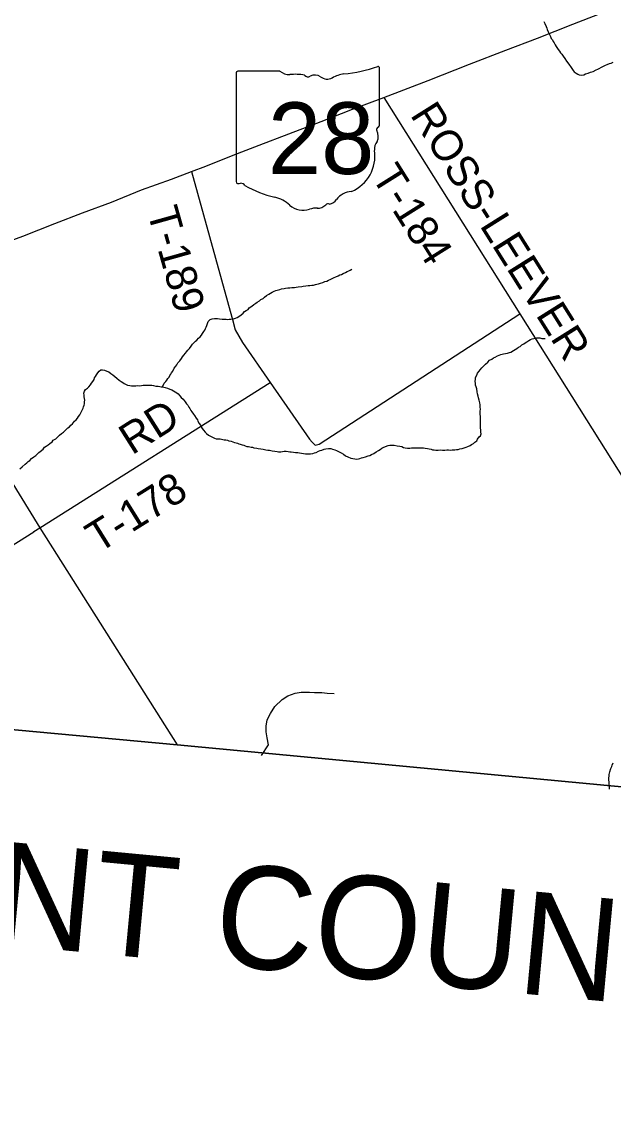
# Model space of a CAD drawing. Extents: x 1310247 to 1664935, y 284496 to 704931.
# Drawn here: x 1527609 to 1533358, y 458214 to 468911 of the extents above; entities that cross this region are included whole.
import ezdxf

# ---------------------------------------------------------------- set-up
doc = ezdxf.new("R2010")
doc.units = 0
for name, color, linetype in [('GM_X_Adjacent_County', 7, 'Continuous'), ('GM_X_Adjacent_County_Text', 7, 'Continuous'), ('GM_X_Airport_Class_2', 7, 'Continuous'), ('GM_X_County_Subdivision_Text', 7, 'Continuous'), ('GM_X_Interstate_Shield', 7, 'Continuous'), ('GM_X_Minor_Lake', 7, 'Continuous'), ('GM_X_Minor_River_Text', 7, 'Continuous'), ('GM_X_Township', 7, 'Continuous'), ('GM_X_Township_Subdivision', 7, 'Continuous'), ('GM_X_Unincorporated_Location', 7, 'Continuous')]:
    doc.layers.add(name, color=color, linetype=linetype)

msp = doc.modelspace()

# ---------------------------------------------------------------- linework, layer by layer
at = {"layer": 'GM_X_Adjacent_County'}
msp.add_lwpolyline([(1543818, 482923), (1543136, 476031), (1542849, 473143), (1542090, 465215), (1541846, 462655), (1541796, 462135), (1541666, 460788), (1541653, 460642), (1541041, 460701), (1540690, 460735), (1539583, 460843), (1534847, 461340), (1529119, 461882), (1524835, 462277), (1522527, 462501), (1521474, 462603)], dxfattribs=at)
at = {"layer": 'GM_X_Adjacent_County_Text'}
msp.add_lwpolyline([(1521474, 462603), (1522527, 462501), (1524835, 462277), (1529119, 461882), (1534847, 461340), (1539583, 460843), (1540690, 460735), (1541041, 460701), (1541653, 460642), (1544018, 460420), (1546591, 460177), (1546362, 457943), (1546170, 456232), (1545962, 454406), (1545594, 451170), (1544985, 445811), (1544696, 443260)], dxfattribs=at)
at = {"layer": 'GM_X_Airport_Class_2'}
for p, q in [((1529694, 468415), (1529694, 467359)), ((1530116, 468434), (1529708, 468434)), ((1531086, 467907), (1531086, 468460)), ((1531086, 467907), (1531086, 467907))]:
    msp.add_line(p, q, dxfattribs=at)
for centre, radius, start, end in [((1529710, 468418), 16.1, 98.1301, 188.1301), ((1530213, 468556), 156, 231.6195, 271.1119), ((1530265, 467840), 562, 80.4867, 94.9883), ((1530458, 468301), 93.8, 54.4667, 119.1411), ((1530779, 468111), 297, 97.3462, 120.7689), ((1530591, 469874), 1476, 275.8445, 288.9065), ((1531071, 468462), 15.5, 351.8621, 97.738), ((1530392, 468423), 45.1, 219.7921, 297.1024), ((1530580, 468469), 113, 233.8562, 294.8282), ((1531083, 467866), 24, 107.944, 210.337), ((1531070, 467905), 16.6, 289.6038, 7.7341), ((1530930, 467797), 144, 340.033, 23.6496), ((1530673, 467605), 369, 292.3089, 8.9858), ((1531142, 467676), 105, 136.8065, 186.9296), ((1529710, 467357), 16.3, 171.9584, 258.3066), ((1529713, 467465), 124, 267.339, 280.6039), ((1529738, 467298), 44.8, 29.7484, 93.2717), ((1530304, 468247), 1066, 240.4129, 257.1985), ((1530829, 467062), 202, 94.4031, 142.5768), ((1529986, 466884), 334, 47.1842, 75.836), ((1530347, 467293), 212, 230.7004, 286.2918), ((1530484, 467213), 113, 268.777, 315.5493), ((1530586, 467111), 31.8, 65.7517, 132.6484), ((1530573, 467256), 119, 282.8732, 323.2771), ((1530469, 466927), 174, 85.6951, 111.2099)]:
    msp.add_arc(centre, radius, start, end, dxfattribs=at)
at = {"layer": 'GM_X_County_Subdivision_Text'}
for points in [[(1531129, 468176), (1532451, 466074), (1535210, 461689)], [(1529258, 467457), (1529667, 465982)], [(1526336, 466341), (1526336, 466341), (1527783, 463992), (1529119, 461882)], [(1529667, 465982), (1529667, 465980), (1529684, 465919), (1529753, 465793), (1530022, 465405), (1530405, 464855), (1530432, 464824), (1530462, 464796), (1530500, 464807), (1532451, 466074)], [(1527724, 463955), (1527783, 463992), (1530022, 465405)], [(1524835, 462277), (1525361, 462592), (1525430, 462635), (1525465, 462681), (1525590, 462787), (1525745, 462831), (1525930, 462854), (1526108, 462936), (1527723, 463954), (1527724, 463955)]]:
    msp.add_lwpolyline(points, dxfattribs=at)
at = {"layer": 'GM_X_Interstate_Shield'}
msp.add_lwpolyline([(1527342, 466727), (1527618, 466829), (1527930, 466951), (1528199, 467054), (1528480, 467158), (1528773, 467280), (1529062, 467383), (1529258, 467457), (1529396, 467510), (1529663, 467617), (1529915, 467712), (1530205, 467824), (1530518, 467944), (1530824, 468064), (1531129, 468176), (1531559, 468342), (1531962, 468500), (1532316, 468638), (1532622, 468754), (1532966, 468889), (1533328, 469029)], dxfattribs=at)
at = {"layer": 'GM_X_Minor_River_Text'}
for points in [[(1532684, 468916), (1532694, 468896), (1532707, 468867), (1532715, 468851), (1532718, 468837), (1532728, 468816), (1532737, 468796), (1532749, 468770), (1532758, 468752), (1532768, 468737), (1532776, 468721), (1532787, 468707), (1532795, 468688), (1532805, 468672), (1532824, 468642), (1532836, 468627), (1532847, 468611), (1532859, 468597), (1532873, 468580), (1532888, 468556), (1532906, 468531), (1532919, 468515), (1532935, 468492), (1532944, 468478), (1532956, 468460), (1532972, 468439), (1532981, 468425), (1533001, 468413), (1533015, 468404), (1533029, 468398), (1533053, 468393), (1533073, 468397), (1533091, 468406), (1533116, 468414), (1533140, 468423), (1533166, 468431)], [(1533166, 468431), (1533195, 468446), (1533209, 468452), (1533223, 468459), (1533246, 468471), (1533272, 468486), (1533286, 468492), (1533302, 468496), (1533323, 468507), (1533339, 468511), (1533359, 468520)], [(1530608, 466408), (1530627, 466417), (1530645, 466425), (1530663, 466432), (1530686, 466442), (1530700, 466452), (1530716, 466455), (1530734, 466465), (1530757, 466474), (1530773, 466484), (1530787, 466492), (1530802, 466499), (1530818, 466509)], [(1528977, 465362), (1528992, 465399), (1529007, 465415), (1529017, 465429), (1529029, 465445), (1529040, 465458), (1529048, 465472), (1529057, 465486), (1529065, 465500), (1529077, 465516), (1529090, 465545), (1529107, 465563), (1529117, 465577), (1529126, 465595), (1529144, 465616), (1529161, 465640), (1529169, 465656), (1529184, 465670), (1529200, 465691), (1529209, 465705), (1529221, 465719), (1529238, 465736), (1529254, 465758), (1529269, 465778), (1529281, 465792), (1529296, 465807), (1529310, 465817), (1529325, 465837), (1529341, 465850), (1529355, 465866), (1529364, 465882), (1529378, 465900), (1529389, 465915), (1529395, 465929), (1529402, 465945), (1529406, 465959), (1529413, 465979), (1529419, 465997), (1529440, 466017), (1529460, 466026), (1529482, 466028), (1529496, 466027), (1529510, 466027), (1529532, 466024), (1529558, 466022), (1529580, 466021), (1529596, 466021), (1529610, 466018), (1529624, 466020), (1529641, 466020), (1529667, 466025), (1529687, 466031), (1529701, 466038), (1529720, 466048), (1529742, 466063), (1529761, 466081), (1529775, 466095), (1529791, 466106), (1529808, 466116), (1529818, 466130), (1529845, 466149), (1529863, 466165), (1529884, 466176), (1529898, 466188), (1529918, 466200), (1529933, 466211), (1529955, 466223), (1529969, 466236), (1529988, 466250), (1530010, 466264), (1530027, 466275), (1530043, 466283), (1530063, 466294), (1530077, 466300), (1530092, 466304), (1530116, 466311), (1530134, 466315), (1530160, 466320), (1530174, 466322), (1530195, 466325), (1530213, 466327), (1530233, 466328), (1530261, 466330), (1530275, 466331), (1530297, 466335), (1530330, 466338), (1530344, 466342), (1530370, 466345), (1530394, 466349), (1530408, 466348), (1530430, 466352), (1530446, 466353), (1530463, 466357), (1530477, 466361), (1530493, 466366), (1530513, 466370), (1530535, 466377), (1530556, 466387), (1530574, 466392), (1530592, 466400), (1530608, 466408)], [(1532038, 465316), (1532032, 465344), (1532027, 465364), (1532021, 465380), (1532020, 465398), (1532018, 465415), (1532019, 465439), (1532021, 465453), (1532032, 465476), (1532040, 465496), (1532055, 465516), (1532067, 465530), (1532082, 465549), (1532098, 465565), (1532119, 465583), (1532139, 465602), (1532158, 465622), (1532180, 465633), (1532195, 465645), (1532211, 465653), (1532235, 465664), (1532251, 465670), (1532268, 465677), (1532292, 465683), (1532312, 465686), (1532332, 465692), (1532351, 465697), (1532365, 465701), (1532391, 465715), (1532405, 465726), (1532424, 465736), (1532438, 465748), (1532454, 465757), (1532471, 465771), (1532489, 465782), (1532504, 465792), (1532520, 465802), (1532538, 465813), (1532555, 465823), (1532573, 465831), (1532587, 465834), (1532601, 465838), (1532615, 465840), (1532629, 465839), (1532647, 465839), (1532665, 465834), (1532683, 465832), (1532699, 465834)], [(1527589, 464566), (1527612, 464586), (1527641, 464611), (1527655, 464623), (1527671, 464637), (1527686, 464648), (1527702, 464666), (1527723, 464681), (1527745, 464697), (1527760, 464713), (1527772, 464726), (1527786, 464734), (1527815, 464758), (1527829, 464775), (1527846, 464787), (1527864, 464798), (1527881, 464812), (1527903, 464830), (1527914, 464843), (1527938, 464859), (1527957, 464878), (1527973, 464892), (1527994, 464908), (1528012, 464923), (1528030, 464939), (1528055, 464964), (1528072, 464974), (1528084, 464992), (1528102, 465005), (1528121, 465029), (1528136, 465043), (1528148, 465058), (1528158, 465076), (1528171, 465092), (1528181, 465110), (1528192, 465130), (1528203, 465155), (1528209, 465169), (1528213, 465185), (1528216, 465199), (1528218, 465217), (1528219, 465235), (1528217, 465251), (1528215, 465266), (1528214, 465282), (1528212, 465302), (1528217, 465320), (1528227, 465337), (1528246, 465351), (1528260, 465363), (1528277, 465384), (1528285, 465398), (1528298, 465416), (1528310, 465436), (1528316, 465450), (1528325, 465464), (1528335, 465481), (1528348, 465499), (1528360, 465515), (1528375, 465527), (1528393, 465528), (1528411, 465526), (1528435, 465517), (1528453, 465509), (1528474, 465494), (1528492, 465480), (1528512, 465465), (1528533, 465446), (1528555, 465428), (1528573, 465415), (1528589, 465405), (1528602, 465397), (1528616, 465390), (1528636, 465380), (1528658, 465375), (1528676, 465373), (1528702, 465372), (1528716, 465374), (1528736, 465375), (1528752, 465373), (1528771, 465375), (1528787, 465378), (1528805, 465380), (1528827, 465381)], [(1528827, 465381), (1528847, 465381), (1528871, 465378), (1528889, 465376), (1528911, 465371), (1528935, 465369), (1528949, 465366), (1528963, 465364), (1528977, 465362), (1529001, 465357), (1529025, 465350), (1529047, 465342), (1529067, 465333), (1529083, 465325), (1529099, 465314), (1529116, 465304), (1529130, 465294), (1529146, 465275), (1529159, 465261), (1529177, 465242), (1529195, 465218), (1529208, 465199), (1529222, 465185), (1529233, 465167), (1529241, 465152), (1529253, 465134), (1529262, 465120), (1529278, 465097), (1529288, 465083), (1529303, 465059), (1529315, 465042), (1529320, 465028), (1529334, 465008), (1529346, 464989), (1529353, 464975), (1529363, 464959), (1529374, 464941), (1529390, 464922), (1529404, 464908), (1529423, 464893), (1529449, 464879), (1529483, 464864), (1529497, 464859), (1529511, 464859), (1529537, 464856), (1529551, 464854), (1529575, 464849), (1529593, 464847), (1529607, 464845), (1529621, 464838), (1529645, 464834), (1529661, 464829), (1529675, 464823), (1529691, 464819), (1529705, 464814), (1529719, 464810), (1529733, 464806), (1529751, 464799), (1529767, 464795), (1529781, 464790), (1529796, 464784), (1529812, 464782), (1529838, 464777), (1529852, 464775), (1529866, 464770), (1529894, 464766), (1529908, 464763), (1529932, 464761), (1529956, 464758), (1529982, 464751), (1530000, 464747), (1530016, 464747), (1530042, 464740), (1530070, 464737), (1530090, 464733), (1530104, 464732), (1530127, 464730), (1530143, 464735), (1530161, 464737), (1530179, 464737), (1530197, 464734), (1530215, 464732), (1530229, 464731), (1530249, 464729), (1530271, 464726), (1530293, 464724), (1530307, 464721), (1530329, 464719), (1530349, 464714), (1530367, 464712), (1530381, 464712), (1530401, 464711), (1530417, 464713), (1530438, 464716), (1530454, 464720), (1530470, 464726), (1530492, 464737), (1530509, 464743), (1530525, 464748), (1530547, 464756), (1530565, 464759)], [(1530565, 464759), (1530591, 464763), (1530612, 464764), (1530631, 464758), (1530653, 464751), (1530669, 464745), (1530695, 464730), (1530715, 464720), (1530737, 464709), (1530756, 464693), (1530778, 464684), (1530808, 464671), (1530828, 464665), (1530846, 464662), (1530862, 464660), (1530882, 464663), (1530896, 464667), (1530913, 464673), (1530927, 464676), (1530951, 464684), (1530977, 464691), (1530992, 464697), (1531008, 464705), (1531030, 464714), (1531055, 464732), (1531077, 464743), (1531093, 464753), (1531108, 464766), (1531122, 464772), (1531144, 464784), (1531171, 464793), (1531187, 464795), (1531205, 464796), (1531229, 464796), (1531257, 464791), (1531285, 464786), (1531303, 464784), (1531319, 464773), (1531337, 464769), (1531359, 464768), (1531383, 464768), (1531399, 464769), (1531419, 464771), (1531437, 464770), (1531451, 464770), (1531478, 464771), (1531498, 464769), (1531514, 464769), (1531530, 464766), (1531552, 464764), (1531570, 464761), (1531588, 464757), (1531602, 464752), (1531620, 464750), (1531636, 464748), (1531656, 464747), (1531680, 464749), (1531700, 464748), (1531722, 464748), (1531740, 464749), (1531758, 464749), (1531776, 464748), (1531792, 464750), (1531821, 464751), (1531835, 464753), (1531851, 464754), (1531869, 464760), (1531891, 464763), (1531911, 464769), (1531930, 464777), (1531946, 464782), (1531968, 464794), (1531983, 464801), (1532001, 464813), (1532015, 464825), (1532032, 464838), (1532040, 464854), (1532055, 464876), (1532069, 464886), (1532074, 464906), (1532072, 464922), (1532071, 464946), (1532069, 464960), (1532068, 464986), (1532068, 465004), (1532068, 465020), (1532069, 465042), (1532069, 465056), (1532068, 465076), (1532066, 465098), (1532067, 465112), (1532067, 465128), (1532068, 465146), (1532066, 465165), (1532065, 465189), (1532061, 465207), (1532056, 465233), (1532050, 465255), (1532047, 465271), (1532041, 465294), (1532038, 465316)], [(1529939, 461778), (1530006, 461881), (1529995, 461949), (1529984, 462008), (1529983, 462062), (1529994, 462126), (1530026, 462186), (1530069, 462255), (1530139, 462322), (1530196, 462359), (1530265, 462384), (1530324, 462395), (1530405, 462393), (1530455, 462392), (1530526, 462391), (1530578, 462386), (1530646, 462382)], [(1533324, 461452), (1533316, 461559), (1533320, 461579), (1533322, 461595), (1533327, 461619), (1533338, 461653), (1533346, 461670), (1533351, 461684), (1533359, 461708)]]:
    msp.add_lwpolyline(points, dxfattribs=at)
at = {"layer": 'GM_X_Township'}
msp.add_lwpolyline([(1543818, 482923), (1543136, 476031), (1542849, 473143), (1542090, 465215), (1541846, 462655), (1541796, 462135), (1541666, 460788), (1541653, 460642), (1541041, 460701), (1540690, 460735), (1539583, 460843), (1534847, 461340), (1529119, 461882), (1524835, 462277), (1522527, 462501), (1521474, 462603)], dxfattribs=at)

# ---------------------------------------------------------------- texts
at = {"layer": 'GM_X_Airport_Class_2'}
msp.add_text('28', height=696.1, dxfattribs=at).set_placement((1530001, 467433))
at = {"layer": 'GM_X_Minor_Lake'}
msp.add_text('CLERMONT COUNTY', height=1000, rotation=354.6098, dxfattribs=at).set_placement((1521612, 460488))
at = {"layer": 'GM_X_Township_Subdivision'}
for s, rotation, p in [('ROSS-LEEVER', 302.1246, (1531380, 468008)), ('T-184', 302.1259, (1531002, 467409)), ('T-189', 285.6749, (1528825, 467070)), ('RD', 32.3198, (1528679, 464695)), ('T-178', 31.975, (1528353, 463741))]:
    msp.add_text(s, height=300, rotation=rotation, dxfattribs=at).set_placement(p)
at = {"layer": 'GM_X_Unincorporated_Location'}
for s in ['s', 'r']:
    msp.add_text(s, height=1, dxfattribs=at).set_placement((1530375, 467817))
msp.add_text('28', height=1, rotation=0, dxfattribs=at).set_placement((1530123, 467744))

doc.saveas('drawing.dxf')
